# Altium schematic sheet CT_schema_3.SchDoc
size 461 x 327 mm
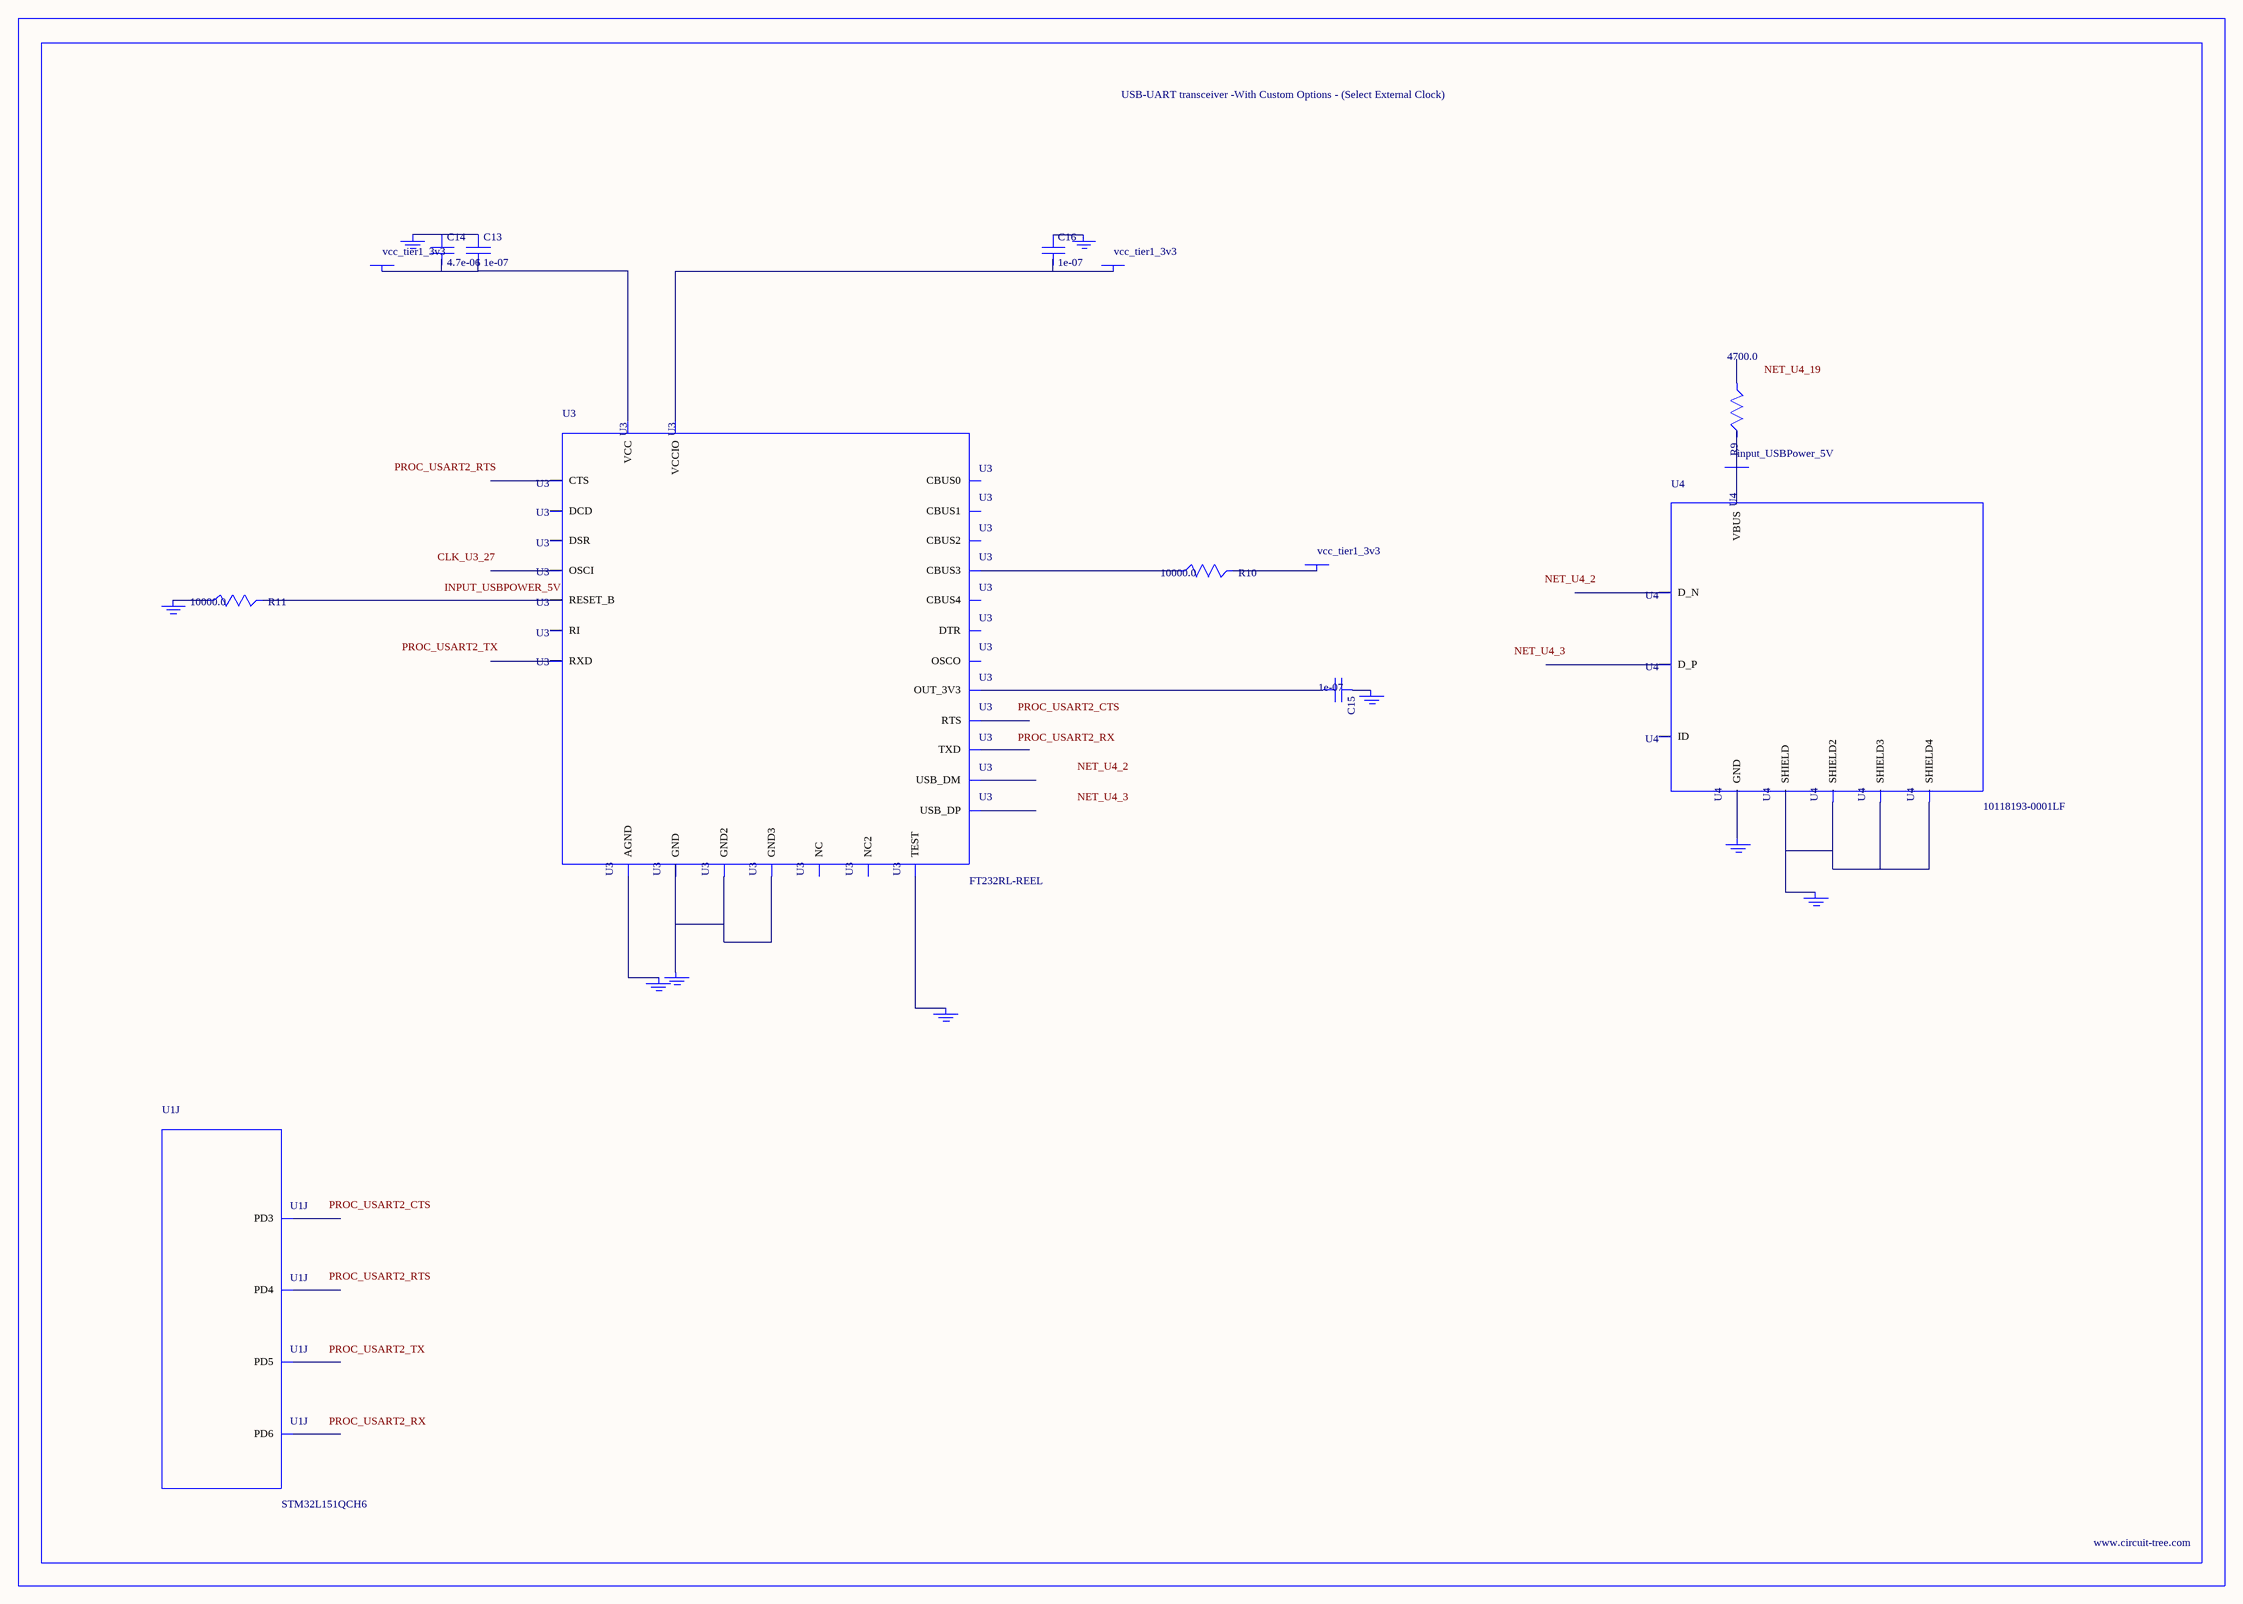
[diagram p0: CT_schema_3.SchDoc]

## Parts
BORDER2  (no value)
C13  1e-07  [C0402]
C14  4.7e-06  [C0805]
C15  1e-07  [C0402]
C16  1e-07  [C0402]
GND_INSTANCE_2_0  (no value)
GND_INSTANCE_2_1  (no value)
GND_INSTANCE_2_2  (no value)
GND_INSTANCE_2_3  (no value)
GND_INSTANCE_2_4  (no value)
GND_INSTANCE_2_5  (no value)
GND_INSTANCE_2_6  (no value)
GND_INSTANCE_2_7  (no value)
GND_INSTANCE_2_8  (no value)
POWER_INSTANCE_2_0  vcc_tier1_3v3
POWER_INSTANCE_2_1  vcc_tier1_3v3
POWER_INSTANCE_2_2  vcc_tier1_3v3
POWER_INSTANCE_2_3  input_USBPower_5V
R9  4700.0  [R0603]
R10  10000.0  [R0603]
R11  10000.0  [R0603]
U1  STM32L151QCH6  [UFBGA132]  (part J of 12)
U3  FT232RL-REEL  [SSOP-28]
U4  10118193-0001LF  [FCI_10118193-0001LF]

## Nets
NetC13_1: C13.1 C14.1 GND_INSTANCE_2_3.0(GND)
NetC13_2: C13.2 C14.2 POWER_INSTANCE_2_2.0(PWR) U3.20(VCC)
NetC15_1: C15.1 GND_INSTANCE_2_1.0(GND)
NetC15_2: C15.2 U3.17(OUT_3V3)
NetC16_1: C16.1 GND_INSTANCE_2_0.0(GND)
NetC16_2: C16.2 POWER_INSTANCE_2_0.0(PWR) U3.4(VCCIO)
NetGND_INSTANCE_2_2_0: GND_INSTANCE_2_2.0(GND) R11.1
NetGND_INSTANCE_2_4_0: GND_INSTANCE_2_4.0(GND) U3.25(AGND)
NetGND_INSTANCE_2_5_0: GND_INSTANCE_2_5.0(GND) U3.26(TEST)
NetGND_INSTANCE_2_6_0: GND_INSTANCE_2_6.0(GND) U3.7(GND) U3.18(GND2) U3.21(GND3)
NetGND_INSTANCE_2_7_0: GND_INSTANCE_2_7.0(GND) U4.6(SHIELD) U4.7(SHIELD2) U4.8(SHIELD3) U4.9(SHIELD4)
NetGND_INSTANCE_2_8_0: GND_INSTANCE_2_8.0(GND) U4.5(GND)
NetPOWER_INSTANCE_2_1_0: POWER_INSTANCE_2_1.0(PWR) R10.2
NetPOWER_INSTANCE_2_3_0: POWER_INSTANCE_2_3.0(PWR) R9.2 U4.1(VBUS)
NetR10_1: R10.1 U3.14(CBUS3)
NetR11_2: R11.2 U3.19(RESET_B)

Not connected (* = marked no-connect by the designer): R9 1; U1 A6(PD5) B6(PD6) B7(PD4) B8(PD3); U3 1(TXD) 2(DTR) 3(RTS) 5(RXD) 6(RI) 8(NC) 9(DSR) 10(DCD) 11(CTS) 12(CBUS4) 13(CBUS2) 15(USB_DP) 16(USB_DM) 22(CBUS1) 23(CBUS0) 24(NC2) 27(OSCI) 28(OSCO); U4 2(D_N) 3(D_P) 4(ID)

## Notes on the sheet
- Labels drawn without touching a wire or pin: CLK_U3_27, INPUT_USBPOWER_5V, NET_U4_2, NET_U4_3, NET_U4_19, PROC_USART2_CTS, PROC_USART2_RTS, PROC_USART2_RX, PROC_USART2_TX

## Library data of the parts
BORDER2 = BORDER_PAGE2
C13 C15 C16 = C0402C104K3RACTU
C14 = C0805C475K4RACTU
GND_INSTANCE_2_0-GND_INSTANCE_2_8 = GND
POWER_INSTANCE_2_0-POWER_INSTANCE_2_3 = PWR
R9 = RC0603JR-074K7L
R10 R11 = RC0603JR-0710KL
